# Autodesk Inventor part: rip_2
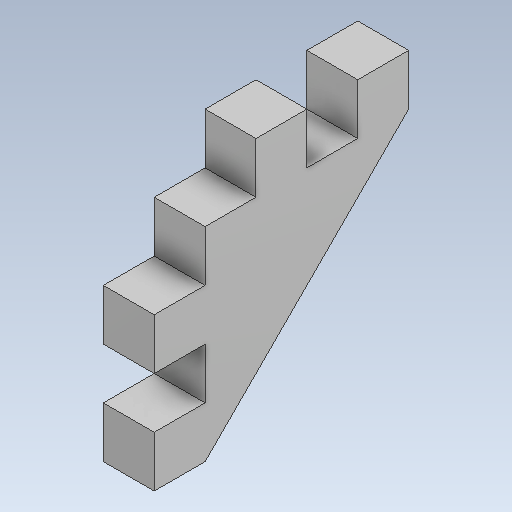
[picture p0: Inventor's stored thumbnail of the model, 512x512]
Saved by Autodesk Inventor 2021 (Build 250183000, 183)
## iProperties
Created: 2026-10
Part Number: rip_2
Material: Generic
Document SubType Name: Modeling
Designer: hp
Density: 1 g/cm^3
Appearance: Default
Author: hp
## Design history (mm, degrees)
feature "Body1"
body "Solid1"
